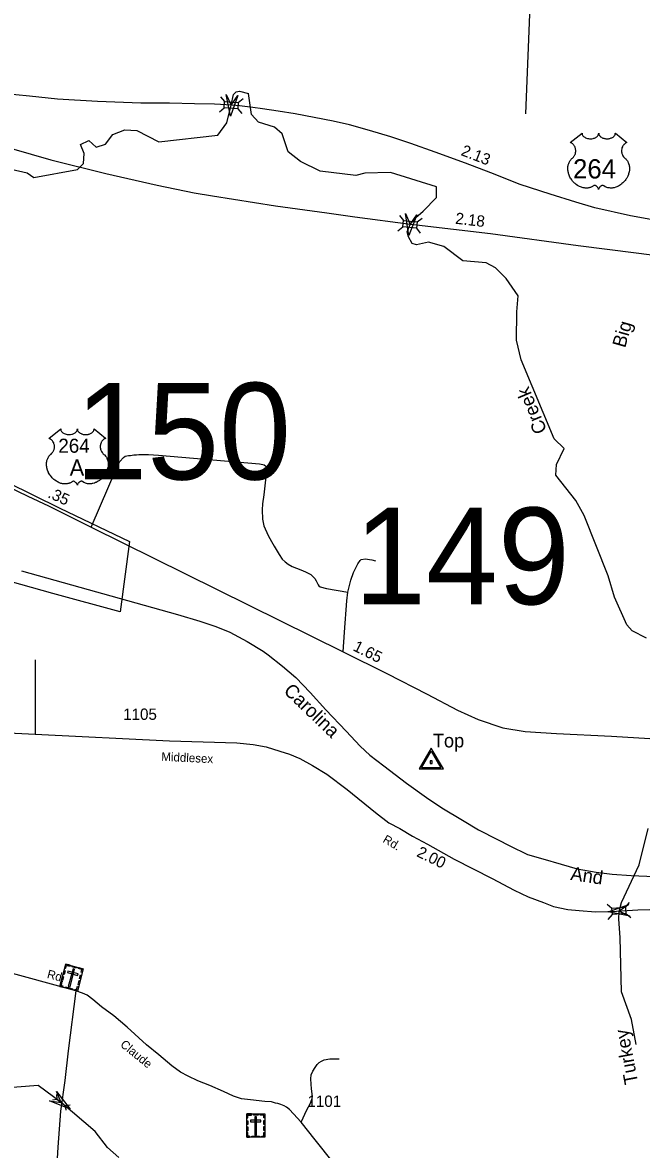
# Model space of a CAD drawing. Extents: x 2220236 to 2384410, y 720751 to 894131.
# Drawn here: x 2241927 to 2248753, y 735017 to 747450 of the extents above; entities that cross this region are included whole.
import ezdxf

# ---------------------------------------------------------------- set-up
doc = ezdxf.new("R2010")
doc.units = 0
doc.layers.add('Default', color=7, linetype='Continuous')

msp = doc.modelspace()

# ---------------------------------------------------------------- linework, layer by layer
at = {"layer": 'Default'}
for p, q in [((2247562, 748687), (2247474, 746445)), ((2244111, 746631), (2244156, 746579)), ((2244306, 746567), (2244359, 746612)), ((2244098, 746464), (2244150, 746508)), ((2244301, 746498), (2244346, 746446)), ((2246086, 745320), (2246129, 745267)), ((2246279, 745250), (2246333, 745293)), ((2246067, 745153), (2246121, 745196)), ((2246271, 745181), (2246314, 745127)), ((2242068, 740418), (2242067, 739599)), ((2248374, 737723), (2248426, 737678)), ((2248577, 737689), (2248622, 737742)), ((2248387, 737555), (2248432, 737608)), ((2248582, 737621), (2248635, 737576)), ((2242256, 735566), (2242306, 735573)), ((2242302, 735624), (2242306, 735573)), ((2242306, 735573), (2242402, 735499)), ((2242452, 735507), (2242402, 735499)), ((2242407, 735449), (2242402, 735499))]:
    msp.add_line(p, q, dxfattribs=at)
for points in [[(2241636, 745798), (2241802, 745831), (2241977, 745791), (2242053, 745740), (2242535, 745829), (2242601, 745896), (2242608, 746005), (2242566, 746104), (2242657, 746148), (2242741, 746074), (2242841, 746108), (2242923, 746215), (2243056, 746268), (2243189, 746258), (2243432, 746135), (2244081, 746207), (2244180, 746343), (2244229, 746538), (2244255, 746657), (2244282, 746686), (2244319, 746694), (2244419, 746669)], [(2244239, 746539), (2244044, 746549), (2243824, 746555), (2243549, 746560), (2243233, 746562), (2242753, 746581), (2242311, 746605), (2242004, 746637), (2241703, 746666)], [(2247899, 742750), (2247790, 742858), (2247425, 743728), (2247373, 743945), (2247379, 744260), (2247394, 744437), (2247259, 744627), (2247142, 744744), (2247041, 744798), (2246783, 744823), (2246573, 744978), (2246406, 745028), (2246270, 744999), (2246224, 745013), (2246182, 745086), (2246168, 745142), (2246201, 745223), (2246264, 745300), (2246345, 745370), (2246494, 745521), (2246493, 745636), (2245984, 745797), (2245701, 745787), (2245601, 745763), (2245209, 745810), (2244992, 745916), (2244857, 746024), (2244789, 746222), (2244705, 746296), (2244530, 746352), (2244454, 746436), (2244419, 746669)], [(2249119, 745229), (2248630, 745317), (2248239, 745406), (2248028, 745468), (2247746, 745556), (2247415, 745663), (2247093, 745791), (2246813, 745900), (2246478, 746021), (2246209, 746115), (2245987, 746188), (2245752, 746261), (2245532, 746320), (2245353, 746361), (2245144, 746404), (2244935, 746444), (2244747, 746474), (2244574, 746498), (2244467, 746513), (2244320, 746532), (2244239, 746539)], [(2240902, 746353), (2241384, 746197), (2241805, 746062), (2242240, 745936), (2242845, 745786), (2243412, 745656), (2243820, 745573), (2244021, 745539), (2244717, 745428), (2245283, 745351), (2245592, 745306), (2246207, 745225), (2246271, 745217)], [(2246271, 745217), (2247089, 745122), (2248053, 744992), (2248696, 744909), (2249640, 744787), (2250015, 744731), (2250395, 744678), (2250801, 744601), (2251191, 744531)], [(2242684, 741882), (2242970, 742550), (2243000, 742608), (2243039, 742652), (2243059, 742667), (2243095, 742675), (2243117, 742675), (2243153, 742681), (2243183, 742682), (2243211, 742684), (2243317, 742683), (2243427, 742678), (2244539, 742581), (2244579, 742573), (2244593, 742569), (2244605, 742559), (2244613, 742539), (2244618, 742521), (2244618, 742485), (2244614, 742471), (2244588, 742241), (2244575, 742139), (2244569, 742075), (2244572, 741971), (2244589, 741897), (2244636, 741792), (2244674, 741726), (2244703, 741672), (2244757, 741583), (2244792, 741531), (2244822, 741501), (2244856, 741476), (2244902, 741450), (2244997, 741413), (2245047, 741391), (2245105, 741362), (2245151, 741318), (2245167, 741292), (2245178, 741267), (2245188, 741247), (2245196, 741235), (2245210, 741223), (2245280, 741205), (2245514, 741165)], [(2248808, 740659), (2248649, 740741), (2248590, 740804), (2248454, 741112), (2248386, 741346), (2248122, 742011), (2248029, 742177), (2247810, 742457), (2247817, 742575), (2247899, 742750)], [(2241410, 742459), (2241556, 742415), (2241758, 742336), (2241985, 742224), (2242214, 742120), (2242684, 741882), (2245464, 740507), (2245943, 740267), (2246389, 740039), (2246724, 739864), (2246953, 739760), (2247224, 739668), (2247470, 739628), (2247814, 739605), (2248422, 739578), (2249329, 739522)], [(2241759, 742378), (2242340, 742091), (2243108, 741723), (2243003, 740948), (2242262, 741152), (2241290, 741424)], [(2241759, 742378), (2242340, 742091), (2243108, 741723), (2243003, 740948), (2242262, 741152), (2241290, 741424)], [(2245514, 741165), (2245547, 741300), (2245577, 741382), (2245624, 741480), (2245651, 741516), (2245661, 741526), (2245709, 741533), (2245753, 741527), (2245779, 741521), (2245819, 741510)], [(2241914, 741400), (2243637, 740920), (2243884, 740846), (2244060, 740788), (2244212, 740723), (2244403, 740620), (2244580, 740516), (2244636, 740476), (2244793, 740348), (2244940, 740223), (2245100, 740060), (2245271, 739866), (2245495, 739634), (2245650, 739467), (2245759, 739366), (2245912, 739249), (2246161, 739059), (2246382, 738899)], [(2245464, 740507), (2245478, 740723), (2245505, 741069), (2245514, 741165)], [(2241257, 739638), (2242067, 739599), (2243547, 739527), (2244292, 739503), (2244470, 739485), (2244613, 739459), (2244763, 739413), (2244872, 739379), (2244986, 739330), (2245125, 739252), (2245283, 739159), (2245507, 738990), (2245818, 738736), (2245968, 738622), (2246087, 738558), (2246227, 738475), (2246393, 738384), (2246686, 738221), (2247106, 738006), (2247350, 737879), (2247503, 737804), (2247671, 737741), (2247782, 737697), (2247940, 737666), (2248066, 737653), (2248244, 737640), (2248382, 737643), (2248479, 737648)], [(2246382, 738899), (2246553, 738787), (2246778, 738649), (2246955, 738542), (2247166, 738436), (2247302, 738367), (2247495, 738271), (2247665, 738222), (2247866, 738164), (2248044, 738115), (2248252, 738075), (2248428, 738056), (2248640, 738040), (2248898, 738030)], [(2248694, 736174), (2248642, 736451), (2248531, 736758), (2248518, 737355), (2248502, 737557), (2248505, 737648), (2248533, 737742), (2248728, 738158), (2248825, 738559)], [(2242516, 736767), (2241047, 737169), (2240319, 737376), (2240169, 737417), (2240089, 737443), (2240016, 737472), (2239959, 737503), (2239900, 737557), (2239804, 737674), (2239558, 737980), (2239462, 738120), (2239426, 738177)], [(2248479, 737648), (2248713, 737661), (2250174, 737700), (2250316, 737715), (2250539, 737762), (2250640, 737780), (2250840, 737785), (2251009, 737780), (2251146, 737780), (2251317, 737772)], [(2242516, 736767), (2242431, 736106), (2242394, 735778), (2242347, 735438), (2242317, 735041), (2242294, 734669), (2242287, 734500), (2242310, 734363), (2242365, 734139), (2242467, 733772), (2242503, 733603), (2242513, 733503), (2242514, 733421), (2242510, 733250), (2242503, 733018), (2242497, 732690), (2242487, 732513), (2242474, 732086), (2242461, 731816), (2242453, 731638), (2242442, 731378), (2242430, 731200)], [(2245356, 734869), (2245156, 735122), (2245000, 735319), (2244917, 735410), (2244872, 735457), (2244837, 735484), (2244813, 735500), (2244777, 735514), (2244741, 735524), (2244717, 735529), (2244673, 735543), (2244599, 735548), (2244442, 735565), (2244343, 735575), (2244255, 735606), (2244144, 735658), (2243994, 735723), (2243862, 735775), (2243753, 735826), (2243670, 735871), (2243574, 735940), (2243429, 736060), (2243296, 736171), (2243081, 736365), (2242933, 736492), (2242799, 736591), (2242702, 736671), (2242641, 736718), (2242589, 736741), (2242516, 736767)], [(2245000, 735319), (2245062, 735455), (2245098, 735522), (2245119, 735569), (2245124, 735597), (2245121, 735630), (2245115, 735688), (2245109, 735738), (2245105, 735795), (2245109, 735840), (2245127, 735882), (2245153, 735921), (2245178, 735954), (2245198, 735975), (2245224, 735992), (2245255, 736006), (2245317, 736018), (2245419, 736016)], [(2242990, 734930), (2242865, 735038), (2242730, 735217), (2242354, 735536), (2242101, 735722), (2241577, 735684)]]:
    msp.add_lwpolyline(points, dxfattribs=at)
for points in [[(2244300, 746647), (2244220, 746416), (2244174, 746656), (2244229, 746538)], [(2244156, 746579), (2244306, 746567), (2244301, 746497), (2244150, 746508)], [(2248097, 746230), (2248097, 746224), (2248098, 746218), (2248099, 746215), (2248102, 746208), (2248107, 746201), (2248114, 746194), (2248121, 746188), (2248127, 746184), (2248135, 746180), (2248145, 746175), (2248156, 746172), (2248168, 746170), (2248180, 746168), (2248192, 746168), (2248206, 746169), (2248220, 746172), (2248227, 746174), (2248234, 746176), (2248241, 746179), (2248249, 746183), (2248255, 746187), (2248260, 746191), (2248267, 746197), (2248272, 746204), (2248275, 746208), (2248277, 746212), (2248279, 746219), (2248280, 746223), (2248281, 746230), (2248281, 746224), (2248282, 746220), (2248283, 746217), (2248284, 746213), (2248287, 746207), (2248290, 746203), (2248296, 746196), (2248299, 746192), (2248302, 746190), (2248311, 746184), (2248321, 746179), (2248326, 746176), (2248332, 746175), (2248338, 746173), (2248345, 746171), (2248352, 746170), (2248358, 746169), (2248365, 746168), (2248371, 746168), (2248378, 746168), (2248384, 746169), (2248391, 746169), (2248398, 746171), (2248404, 746172), (2248412, 746174), (2248419, 746177), (2248425, 746179), (2248433, 746183), (2248440, 746187), (2248444, 746191), (2248450, 746196), (2248455, 746203), (2248458, 746207), (2248461, 746212), (2248463, 746217), (2248464, 746222), (2248464, 746226), (2248465, 746230), (2248593, 746128), (2248590, 746126), (2248583, 746123), (2248578, 746120), (2248569, 746113), (2248565, 746110), (2248561, 746106), (2248558, 746103), (2248555, 746099), (2248551, 746094), (2248548, 746089), (2248544, 746083), (2248542, 746078), (2248538, 746068), (2248536, 746061), (2248535, 746056), (2248533, 746044), (2248533, 746039), (2248533, 746033), (2248533, 746028), (2248534, 746022), (2248535, 746017), (2248536, 746011), (2248537, 746005), (2248540, 745998), (2248542, 745991), (2248548, 745980), (2248556, 745969), (2248561, 745962), (2248566, 745957), (2248574, 745950), (2248579, 745946), (2248584, 745941), (2248592, 745932), (2248595, 745928), (2248598, 745923), (2248601, 745918), (2248604, 745912), (2248607, 745907), (2248611, 745896), (2248615, 745886), (2248616, 745880), (2248618, 745867), (2248619, 745861), (2248620, 745849), (2248620, 745834), (2248619, 745820), (2248617, 745803), (2248614, 745793), (2248611, 745782), (2248608, 745772), (2248602, 745757), (2248597, 745747), (2248590, 745734), (2248585, 745727), (2248580, 745719), (2248573, 745709), (2248565, 745700), (2248556, 745689), (2248548, 745681), (2248538, 745673), (2248532, 745668), (2248523, 745661), (2248511, 745653), (2248500, 745646), (2248490, 745641), (2248481, 745637), (2248470, 745633), (2248451, 745628), (2248444, 745626), (2248436, 745625), (2248428, 745624), (2248420, 745624), (2248410, 745624), (2248400, 745625), (2248391, 745626), (2248381, 745628), (2248371, 745631), (2248362, 745635), (2248352, 745639), (2248336, 745649), (2248332, 745652), (2248329, 745653), (2248323, 745653), (2248317, 745652), (2248311, 745649), (2248308, 745647), (2248303, 745644), (2248299, 745641), (2248295, 745637), (2248292, 745634), (2248290, 745631), (2248285, 745624), (2248284, 745621), (2248282, 745616), (2248280, 745610), (2248278, 745618), (2248276, 745623), (2248273, 745628), (2248270, 745632), (2248266, 745637), (2248262, 745641), (2248257, 745645), (2248252, 745648), (2248248, 745650), (2248244, 745652), (2248239, 745653), (2248236, 745653), (2248232, 745653), (2248228, 745652), (2248222, 745648), (2248217, 745644), (2248211, 745640), (2248204, 745636), (2248198, 745634), (2248192, 745632), (2248185, 745629), (2248177, 745627), (2248169, 745625), (2248162, 745624), (2248154, 745624), (2248147, 745623), (2248140, 745624), (2248133, 745624), (2248125, 745625), (2248116, 745626), (2248108, 745628), (2248099, 745630), (2248090, 745633), (2248081, 745637), (2248069, 745642), (2248061, 745646), (2248048, 745653), (2248033, 745664), (2248022, 745673), (2248014, 745680), (2248001, 745693), (2247994, 745701), (2247983, 745716), (2247976, 745726), (2247971, 745734), (2247964, 745746), (2247960, 745754), (2247956, 745766), (2247952, 745776), (2247949, 745786), (2247947, 745792), (2247944, 745803), (2247943, 745811), (2247942, 745822), (2247941, 745833), (2247941, 745843), (2247941, 745852), (2247942, 745862), (2247944, 745873), (2247946, 745882), (2247947, 745889), (2247950, 745897), (2247954, 745906), (2247958, 745914), (2247962, 745921), (2247967, 745929), (2247972, 745935), (2247979, 745942), (2247986, 745949), (2247992, 745954), (2247999, 745961), (2248003, 745966), (2248008, 745972), (2248012, 745978), (2248015, 745983), (2248018, 745990), (2248021, 745996), (2248024, 746005), (2248025, 746011), (2248027, 746018), (2248028, 746026), (2248028, 746035), (2248028, 746043), (2248027, 746051), (2248025, 746060), (2248023, 746067), (2248020, 746076), (2248017, 746082), (2248012, 746091), (2248007, 746098), (2248001, 746105), (2247995, 746111), (2247990, 746115), (2247985, 746118), (2247978, 746122), (2247972, 746126), (2247968, 746127)], [(2246129, 745267), (2246279, 745250), (2246271, 745180), (2246121, 745196)], [(2246276, 745329), (2246186, 745102), (2246151, 745343), (2246201, 745223)], [(2242348, 742966), (2242348, 742960), (2242349, 742954), (2242350, 742951), (2242353, 742945), (2242358, 742937), (2242365, 742930), (2242373, 742924), (2242378, 742920), (2242387, 742916), (2242397, 742912), (2242408, 742908), (2242419, 742906), (2242431, 742905), (2242444, 742904), (2242457, 742905), (2242471, 742908), (2242478, 742910), (2242486, 742913), (2242493, 742916), (2242500, 742920), (2242506, 742924), (2242511, 742927), (2242518, 742934), (2242524, 742940), (2242526, 742944), (2242528, 742948), (2242530, 742956), (2242531, 742959), (2242532, 742966), (2242532, 742960), (2242533, 742956), (2242534, 742953), (2242535, 742949), (2242538, 742943), (2242541, 742939), (2242547, 742932), (2242550, 742929), (2242554, 742926), (2242562, 742920), (2242573, 742915), (2242578, 742913), (2242583, 742911), (2242589, 742909), (2242596, 742907), (2242603, 742906), (2242610, 742905), (2242617, 742905), (2242622, 742904), (2242629, 742905), (2242636, 742905), (2242642, 742906), (2242650, 742907), (2242655, 742908), (2242663, 742910), (2242670, 742913), (2242676, 742915), (2242684, 742920), (2242691, 742924), (2242695, 742927), (2242701, 742933), (2242706, 742939), (2242710, 742943), (2242712, 742948), (2242714, 742953), (2242715, 742958), (2242716, 742962), (2242716, 742966), (2242844, 742864), (2242841, 742863), (2242834, 742859), (2242829, 742856), (2242820, 742850), (2242816, 742846), (2242812, 742843), (2242809, 742839), (2242806, 742835), (2242802, 742830), (2242799, 742825), (2242795, 742819), (2242793, 742814), (2242789, 742804), (2242787, 742797), (2242786, 742792), (2242784, 742780), (2242784, 742775), (2242784, 742770), (2242784, 742764), (2242785, 742758), (2242786, 742753), (2242787, 742748), (2242788, 742742), (2242791, 742734), (2242794, 742728), (2242799, 742716), (2242807, 742705), (2242812, 742699), (2242818, 742693), (2242826, 742686), (2242830, 742683), (2242835, 742678), (2242843, 742668), (2242846, 742664), (2242849, 742659), (2242853, 742654), (2242856, 742648), (2242858, 742644), (2242862, 742633), (2242866, 742622), (2242867, 742616), (2242870, 742604), (2242871, 742597), (2242872, 742585), (2242872, 742570), (2242871, 742556), (2242868, 742540), (2242866, 742530), (2242862, 742518), (2242859, 742508), (2242853, 742494), (2242848, 742483), (2242841, 742471), (2242837, 742463), (2242831, 742455), (2242824, 742446), (2242816, 742436), (2242807, 742425), (2242799, 742418), (2242789, 742409), (2242783, 742404), (2242775, 742397), (2242763, 742389), (2242751, 742383), (2242741, 742377), (2242732, 742374), (2242721, 742369), (2242702, 742364), (2242695, 742363), (2242687, 742361), (2242679, 742361), (2242672, 742360), (2242662, 742360), (2242652, 742361), (2242642, 742362), (2242632, 742364), (2242622, 742367), (2242613, 742371), (2242603, 742376), (2242588, 742386), (2242583, 742388), (2242580, 742389), (2242574, 742389), (2242568, 742388), (2242563, 742386), (2242559, 742384), (2242554, 742381), (2242551, 742378), (2242546, 742373), (2242543, 742370), (2242541, 742367), (2242536, 742360), (2242535, 742357), (2242533, 742353), (2242532, 742346), (2242530, 742354), (2242527, 742360), (2242524, 742364), (2242522, 742368), (2242517, 742373), (2242513, 742377), (2242508, 742381), (2242503, 742384), (2242499, 742386), (2242495, 742388), (2242491, 742389), (2242487, 742389), (2242484, 742389), (2242479, 742388), (2242474, 742384), (2242468, 742380), (2242462, 742376), (2242455, 742373), (2242450, 742370), (2242443, 742368), (2242436, 742365), (2242428, 742363), (2242420, 742362), (2242413, 742361), (2242405, 742360), (2242398, 742360), (2242391, 742360), (2242384, 742360), (2242377, 742361), (2242367, 742362), (2242359, 742364), (2242350, 742366), (2242342, 742369), (2242332, 742373), (2242321, 742378), (2242312, 742382), (2242300, 742389), (2242285, 742400), (2242273, 742409), (2242265, 742417), (2242253, 742429), (2242245, 742437), (2242234, 742452), (2242227, 742462), (2242222, 742470), (2242215, 742483), (2242212, 742490), (2242207, 742502), (2242203, 742512), (2242200, 742522), (2242198, 742528), (2242196, 742539), (2242194, 742547), (2242193, 742558), (2242192, 742569), (2242192, 742580), (2242192, 742588), (2242193, 742598), (2242195, 742609), (2242197, 742618), (2242199, 742625), (2242201, 742633), (2242205, 742642), (2242209, 742650), (2242213, 742657), (2242218, 742665), (2242223, 742672), (2242230, 742679), (2242237, 742685), (2242243, 742690), (2242251, 742698), (2242254, 742702), (2242259, 742708), (2242263, 742714), (2242266, 742719), (2242270, 742726), (2242272, 742732), (2242275, 742741), (2242276, 742747), (2242278, 742755), (2242279, 742762), (2242279, 742771), (2242279, 742779), (2242278, 742788), (2242276, 742796), (2242274, 742804), (2242271, 742812), (2242268, 742818), (2242263, 742827), (2242258, 742835), (2242252, 742841), (2242247, 742847), (2242241, 742851), (2242236, 742855), (2242229, 742859), (2242223, 742862), (2242219, 742863)], [(2246568, 739217), (2246434, 739443), (2246301, 739217)], [(2246542, 739229), (2246327, 739229), (2246434, 739411)], [(2246446, 739276), (2246446, 739304), (2246422, 739304), (2246422, 739276)], [(2248623, 737593), (2248384, 737639), (2248614, 737719), (2248505, 737648)], [(2248426, 737678), (2248577, 737690), (2248582, 737619), (2248432, 737608)], [(2242404, 737062), (2242597, 737011), (2242532, 736765), (2242339, 736816)], [(2242393, 737020), (2242404, 737017), (2242412, 737048), (2242452, 737038), (2242454, 737049), (2242404, 737062)], [(2242476, 737043), (2242526, 737030), (2242523, 737019), (2242473, 737032)], [(2242357, 736884), (2242368, 736925), (2242379, 736923), (2242368, 736881)], [(2242374, 736949), (2242385, 736990), (2242396, 736988), (2242385, 736946)], [(2242426, 736986), (2242422, 736968), (2242535, 736938), (2242540, 736956)], [(2242502, 737006), (2242484, 737011), (2242432, 736815), (2242451, 736810)], [(2242586, 736970), (2242575, 736972), (2242583, 737004), (2242544, 737014), (2242547, 737025), (2242597, 737011)], [(2242556, 736902), (2242567, 736944), (2242578, 736941), (2242567, 736899)], [(2242371, 736808), (2242374, 736819), (2242353, 736824), (2242363, 736863), (2242353, 736866), (2242339, 736816)], [(2242398, 736812), (2242480, 736791), (2242477, 736780), (2242395, 736801)], [(2242500, 736774), (2242503, 736785), (2242524, 736779), (2242534, 736818), (2242545, 736815), (2242532, 736765)], [(2242539, 736838), (2242550, 736880), (2242561, 736877), (2242550, 736835)], [(2242301, 735655), (2242452, 735463), (2242225, 735554), (2242354, 735536)], [(2244399, 735409), (2244598, 735409), (2244598, 735154), (2244399, 735154)], [(2244399, 735365), (2244410, 735365), (2244410, 735397), (2244451, 735397), (2244451, 735409), (2244399, 735409)], [(2244399, 735291), (2244399, 735334), (2244410, 735334), (2244410, 735291)], [(2244440, 735341), (2244440, 735322), (2244557, 735322), (2244557, 735341)], [(2244473, 735409), (2244525, 735409), (2244525, 735397), (2244473, 735397)], [(2244508, 735379), (2244489, 735379), (2244489, 735176), (2244508, 735176)], [(2244598, 735365), (2244587, 735365), (2244587, 735397), (2244546, 735397), (2244546, 735409), (2244598, 735409)], [(2244587, 735292), (2244587, 735335), (2244598, 735335), (2244598, 735292)], [(2244399, 735224), (2244399, 735267), (2244410, 735267), (2244410, 735224)], [(2244432, 735154), (2244432, 735165), (2244410, 735165), (2244410, 735206), (2244399, 735206), (2244399, 735154)], [(2244565, 735154), (2244565, 735165), (2244587, 735165), (2244587, 735206), (2244598, 735206), (2244598, 735154)], [(2244587, 735226), (2244587, 735270), (2244598, 735270), (2244598, 735226)], [(2244456, 735165), (2244541, 735165), (2244541, 735154), (2244456, 735154)]]:
    msp.add_lwpolyline(points, close=True, dxfattribs=at)

# ---------------------------------------------------------------- texts
for s, height, rotation, p in [('2.13', 125, 338.7176, (2246754, 745990)), ('2.18', 125, 353.367, (2246695, 745231)), ('Big', 150, 74.0648, (2248572, 743854)), ('Creek', 150, 112.7575, (2247714, 742949)), ('.35', 125, 335.4976, (2242197, 742215)), ('1.65', 125, 333.4219, (2245563, 740527)), ('Carolina', 150, 316.0973, (2244797, 740066)), ('Middlesex', 95, 357.2534, (2243456, 739306)), ('Rd.', 95, 329.6267, (2245892, 738412)), ('2.00', 125, 333.893, (2246264, 738256)), ('And', 150, 351.5727, (2247964, 737991)), ('Rd.', 95, 345.2678, (2242191, 736911)), ('Turkey', 150, 100.665, (2248717, 735751)), ('Claude', 95, 320.6349, (2242997, 736162))]:
    msp.add_text(s, height=height, rotation=rotation, dxfattribs=at).set_placement(p)
for s, height, p in [('264', 212.5, (2247998, 745730)), ('150', 1066.3, (2242509, 742409)), ('264', 155, (2242322, 742704)), ('A', 180, (2242447, 742450)), ('149', 1066.3, (2245584, 741032)), ('1105', 125, (2243037, 739757)), ('Top', 150, (2246452, 739453)), ('1101', 125, (2245069, 735487))]:
    msp.add_text(s, height=height, dxfattribs=at).set_placement(p)

doc.saveas('drawing.dxf')
